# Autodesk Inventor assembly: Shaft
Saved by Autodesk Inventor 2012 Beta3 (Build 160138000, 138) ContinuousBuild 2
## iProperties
Created: 2010-12
Part Number: Shaft
Document SubType Name: Assembly
Designer: Thom Tremblay
ClientObjectVersion: 1
Author: Thom Tremblay
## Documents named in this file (2)
- C:\Inventor 2012 Essentials\Assemblies\Chapter 6\c6-01\Design Accelerator\Shaft6.iam
- C:\Inventor 2012 Essentials\Assemblies\Chapter 6\c6-01\Design Accelerator\Shaft6.ipt
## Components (1 placed, 1 different names)
1. Shaft:1
